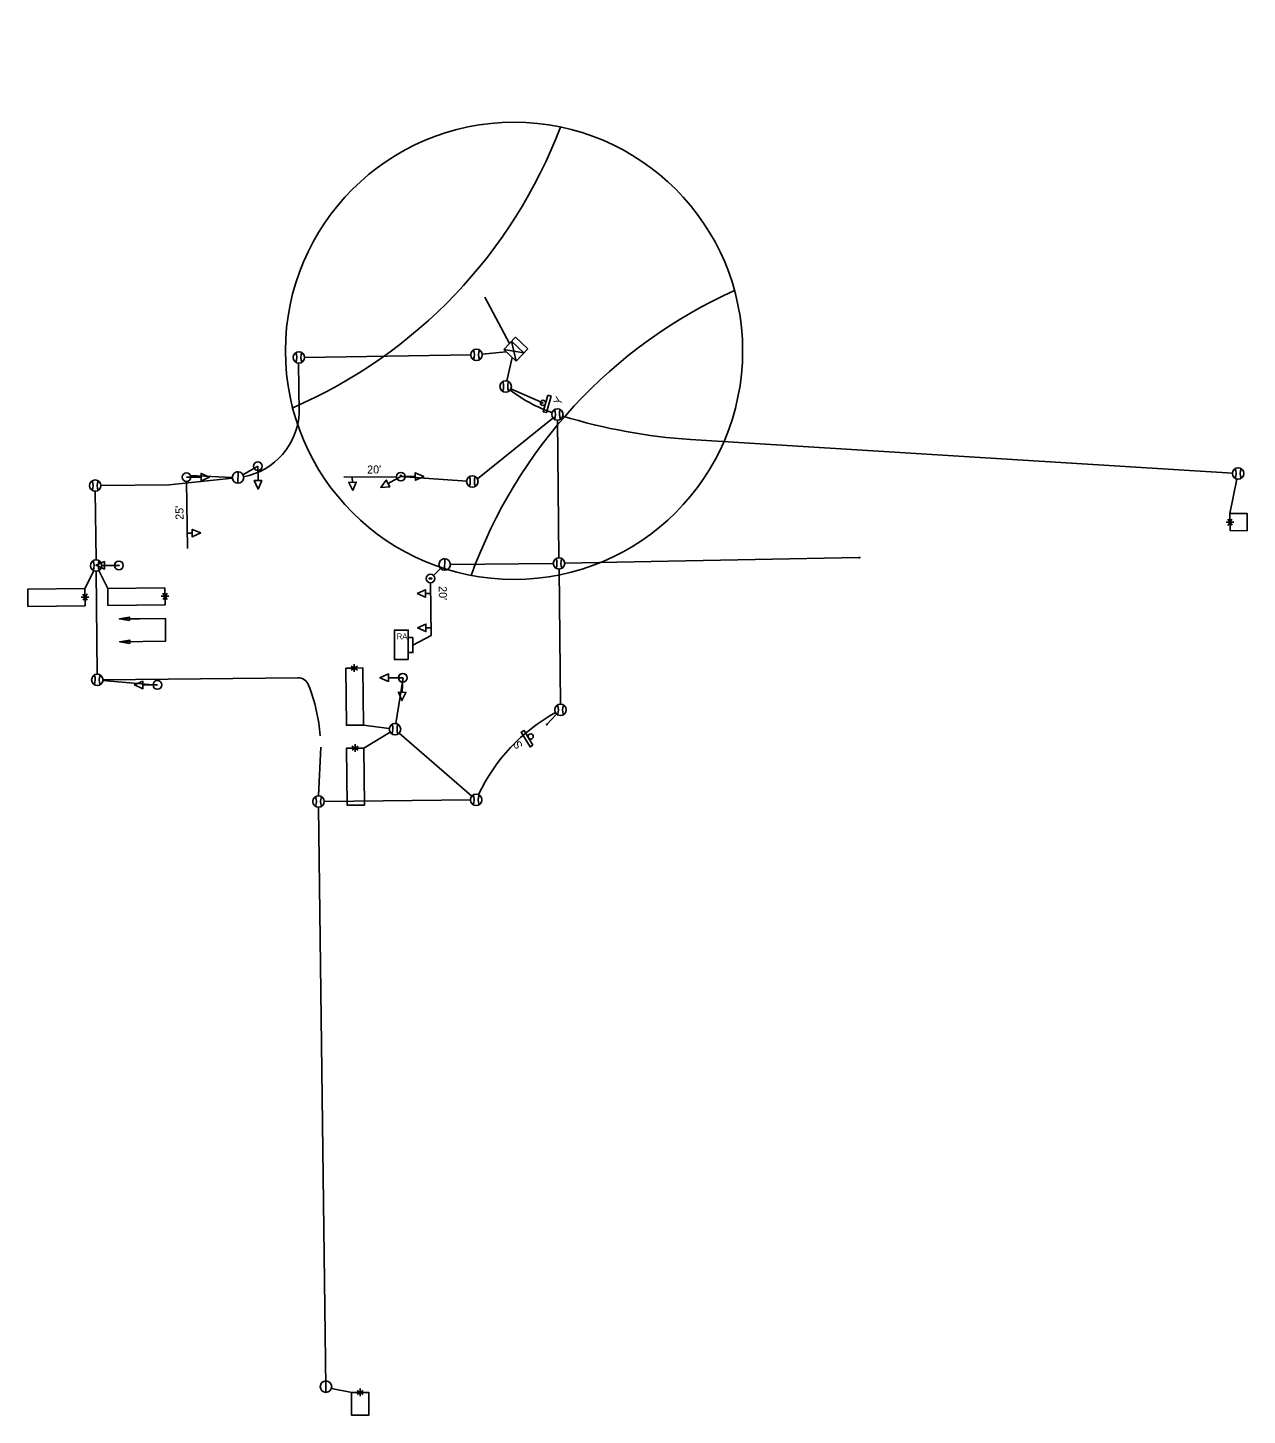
# Model space of a CAD drawing. Extents: x 596176 to 605330, y 332416 to 402398.
# Drawn here: x 602947 to 603373.8, y 387341.9 to 387827.4 of the extents above; entities that cross this region are included whole.
import ezdxf

# ---------------------------------------------------------------- set-up
doc = ezdxf.new("R2010")
doc.units = 0
for name, color, linetype in [('P_LTG', 7, 'Continuous'), ('P_SIG', 7, 'Continuous'), ('P_SIG_Bold', 7, 'Continuous'), ('P_SIG_Conduit', 7, 'Continuous'), ('P_SIG_IC', 7, 'Continuous'), ('P_SIG_Loops', 7, 'Continuous')]:
    doc.layers.add(name, color=color, linetype=linetype)

# ---------------------------------------------------------------- blocks, each defined once
blk = doc.blocks.new('_U305')
at = {"layer": 'P_SIG_Loops'}
for p, q in [((0.1, -0.1), (-0.1, 0.1)), ((-0.1, -0.1), (0.1, 0.1)), ((0, 0), (0, -0.2)), ((-0.1, 0), (0.1, 0))]:
    blk.add_line(p, q, dxfattribs=at)
blk.add_lwpolyline([(0, -0.2), (1.5, -0.2), (1.5, 0.2), (0, 0.2)], close=True, dxfattribs=at)
blk = doc.blocks.new('_U307')
at = {"layer": 'P_SIG_Loops'}
for p, q in [((0, 0), (0, -0.2)), ((0.6, -0.3), (0.5, -0.1)), ((0.5, -0.3), (0.6, -0.1)), ((0.5, -0.2), (0.7, -0.2))]:
    blk.add_line(p, q, dxfattribs=at)
blk.add_lwpolyline([(0, -0.2), (1.1, -0.2), (1.1, 0.2), (0, 0.2)], close=True, dxfattribs=at)
blk = doc.blocks.new('_U300')
at = {"layer": 'P_SIG_Bold'}
for p, q in [((-3, 0), (-0.1, 0)), ((-0.1, 0.1), (0.1, -0.1)), ((0.1, 0.1), (-0.1, -0.1))]:
    blk.add_line(p, q, dxfattribs=at)
blk.add_circle((0, 0), 0.114, dxfattribs=at)
blk.add_text("40'", height=0.213, dxfattribs=at).set_placement((-1.8, 0.1))
blk = doc.blocks.new('_U212')
at = {"layer": 'P_SIG'}
blk.add_circle((-0.002, 0.01), 6.096, dxfattribs=at)
for centre, start, end in [((-15.457, 0.118), 336.6741, 22.5272), ((15.453, 0.146), 157.5751, 203.4282)]:
    blk.add_arc(centre, 13.28, start, end, dxfattribs=at)

msp = doc.modelspace()

# ---------------------------------------------------------------- linework, layer by layer
at = {"layer": 'P_SIG'}
for p, q in [((603113.57, 387714.85), (603117.7, 387719.19)), ((603117.91, 387710.71), (603113.57, 387714.85)), ((603113.57, 387714.85), (603120.67, 387713.61)), ((603116.32, 387717.74), (603120.67, 387713.61)), ((603117.91, 387710.71), (603116.32, 387717.74)), ((603117.7, 387719.19), (603122.05, 387715.06)), ((603122.05, 387715.06), (603117.91, 387710.71)), ((603127.4, 387693.05), (603128.98, 387698.83)), ((603130.14, 387698.52), (603128.55, 387692.73)), ((603128.98, 387698.83), (603130.14, 387698.52)), ((603128.55, 387692.73), (603127.4, 387693.05)), ((603020.6, 387672.01), (603020.57, 387668.01)), ((603027.59, 387668.97), (603027.54, 387674.02)), ((603007.63, 387670.14), (603002.58, 387670.15)), ((603060.63, 387668.38), (603060.58, 387670.15)), ((603073.12, 387667.95), (603077.58, 387670.33)), ((603082.64, 387670.38), (603077.58, 387670.33)), ((603004.56, 387650.57), (603002.79, 387650.54)), ((602973.85, 387639.3), (602978.91, 387639.29)), ((603092.92, 387641.56), (603092.9, 387637.56)), ((603086.24, 387629.44), (603088.02, 387629.44)), ((603081.78, 387611.38), (603088.17, 387614.69)), ((603086.37, 387617.44), (603088.14, 387617.44)), ((603073.2, 387599.97), (603078.26, 387599.95)), ((603078.05, 387594.9), (603078.26, 387599.95)), ((602987.29, 387597.44), (602992.35, 387597.43)), ((603119.67, 387580.88), (603120.69, 387581.5)), ((603122.78, 387575.75), (603119.67, 387580.88)), ((603120.69, 387581.5), (603123.81, 387576.37)), ((603123.81, 387576.37), (603122.78, 387575.75)), ((603051.37, 387353.85), (603051.35, 387349.85))]:
    msp.add_line(p, q, dxfattribs=at)
for points in [[(603128.98, 387698.83), (603130.14, 387698.52), (603128.55, 387692.73), (603127.4, 387693.05)], [(603060.72, 387665.43), (603059.32, 387668.34), (603061.95, 387668.42)], [(603007.52, 387650.62), (603004.58, 387649.25), (603004.54, 387651.89)], [(603083.29, 387629.44), (603086.24, 387630.76), (603086.24, 387628.13)], [(603083.41, 387617.44), (603086.37, 387618.76), (603086.37, 387616.13)], [(603080.15, 387606.29), (603080.15, 387616.64), (603075.32, 387616.64), (603075.32, 387606.29)], [(603081.78, 387614.01), (603080.18, 387614.01), (603080.18, 387608.74), (603081.78, 387608.74)], [(603123.81, 387576.37), (603122.78, 387575.75), (603119.67, 387580.88), (603120.69, 387581.5)]]:
    msp.add_lwpolyline(points, close=True, dxfattribs=at)
for points in [[(603010.59, 387670.14), (603007.63, 387668.82), (603007.63, 387671.46), (603010.59, 387670.14)], [(603010.59, 387670.14), (603007.63, 387668.82), (603007.63, 387671.46), (603010.59, 387670.14)], [(603007.63, 387668.82), (603010.59, 387670.14), (603007.63, 387671.46), (603007.63, 387668.82)], [(603020.57, 387668.01), (603020.6, 387672.01)], [(603085.6, 387670.42), (603082.65, 387669.07), (603082.62, 387671.7), (603085.6, 387670.42)], [(603085.6, 387670.42), (603082.65, 387669.07), (603082.62, 387671.7), (603085.6, 387670.42)], [(603082.65, 387669.07), (603085.6, 387670.42), (603082.62, 387671.7), (603082.65, 387669.07)], [(603027.62, 387666.01), (603026.27, 387668.95), (603028.91, 387668.98), (603027.62, 387666.01)], [(603026.27, 387668.95), (603027.62, 387666.01), (603028.91, 387668.98), (603026.27, 387668.95)], [(603070.51, 387666.55), (603072.49, 387669.11), (603073.74, 387666.79), (603070.51, 387666.55)], [(603070.51, 387666.55), (603072.49, 387669.11), (603073.74, 387666.79), (603070.51, 387666.55)], [(603072.49, 387669.11), (603070.51, 387666.55), (603073.74, 387666.79), (603072.49, 387669.11)], [(602970.89, 387639.3), (602973.85, 387640.62), (602973.85, 387637.98), (602970.89, 387639.3)], [(602973.85, 387640.62), (602970.89, 387639.3), (602973.85, 387637.98), (602973.85, 387640.62)], [(603092.9, 387637.56), (603092.92, 387641.56)], [(602984.33, 387597.44), (602987.29, 387598.76), (602987.29, 387596.12), (602984.33, 387597.44)], [(602987.29, 387598.76), (602984.33, 387597.44), (602987.29, 387596.12), (602987.29, 387598.76)], [(603070.24, 387599.97), (603073.2, 387601.28), (603073.2, 387598.65), (603070.24, 387599.97)], [(603073.2, 387601.28), (603070.24, 387599.97), (603073.2, 387598.65), (603073.2, 387601.28)], [(603077.93, 387591.94), (603076.73, 387594.95), (603079.37, 387594.85), (603077.93, 387591.94)], [(603076.73, 387594.95), (603077.93, 387591.94), (603079.37, 387594.85), (603076.73, 387594.95)], [(603051.35, 387349.85), (603051.37, 387353.85)]]:
    msp.add_lwpolyline(points, dxfattribs=at)
for centre, radius in [((603104.04, 387712.98), 2), ((603041.89, 387712.06), 2), ((603114.25, 387701.88), 2), ((603127.32, 387696.16), 0.9), ((603132.36, 387692.11), 2), ((603020.59, 387670.01), 2), ((603027.54, 387674.02), 1.52), ((603027.54, 387674.02), 1.52), ((603027.54, 387674.02), 1.52), ((603370.59, 387671.45), 2), ((602970.61, 387667.2), 2), ((603102.6, 387668.65), 2), ((603132.91, 387639.98), 2), ((602970.9, 387639.21), 2), ((602978.91, 387639.29), 1.52), ((602978.91, 387639.29), 1.52), ((602978.91, 387639.29), 1.52), ((603092.91, 387639.56), 2), ((602971.33, 387599.2), 2), ((602992.35, 387597.43), 1.52), ((602992.35, 387597.43), 1.52), ((602992.35, 387597.43), 1.52), ((603078.26, 387599.95), 1.52), ((603078.26, 387599.95), 1.52), ((603078.26, 387599.95), 1.52), ((603078.26, 387599.95), 1.52), ((603078.26, 387599.95), 1.52), ((603078.26, 387599.95), 1.52), ((603133.45, 387588.72), 2), ((603075.52, 387581.93), 2), ((603123.01, 387579.41), 0.9), ((603048.78, 387556.64), 2), ((603103.93, 387557.22), 2), ((603051.36, 387351.85), 2)]:
    msp.add_circle(centre, radius, dxfattribs=at)
for centre, radius, start, end in [((603036.82, 387712.1), 4.36, 336.6741, 22.5272), ((603046.97, 387712.11), 4.36, 157.5751, 203.4282), ((603098.97, 387713.01), 4.36, 336.6741, 22.5272), ((603109.11, 387713.02), 4.36, 157.5751, 203.4282), ((603109.18, 387701.92), 4.36, 336.6741, 22.5272), ((603119.32, 387701.93), 4.36, 157.5751, 203.4282), ((603127.29, 387692.14), 4.36, 336.6741, 22.5272), ((603137.43, 387692.15), 4.36, 157.5751, 203.4282), ((603020.59, 387670.01), 2, 89.7008, 180), ((603027.54, 387674.02), 1.52, 90.7054, 270.7054), ((603027.54, 387674.02), 1.52, 270.7054, 90.7054), ((603365.51, 387671.48), 4.36, 336.6741, 22.5272), ((603375.66, 387671.49), 4.36, 157.5751, 203.4282), ((602965.54, 387667.24), 4.36, 336.6741, 22.5272), ((602975.68, 387667.25), 4.36, 157.5751, 203.4282), ((603020.59, 387670.01), 2, 180, 269.7008), ((603097.53, 387668.69), 4.36, 336.6741, 22.5272), ((603107.67, 387668.7), 4.36, 157.5751, 203.4282), ((602965.83, 387639.24), 4.36, 336.6741, 22.5272), ((602975.98, 387639.25), 4.36, 157.5751, 203.4282), ((602978.91, 387639.29), 1.52, 0, 180), ((602978.91, 387639.29), 1.52, 180, 0), ((603092.91, 387639.56), 2, 89.7008, 180), ((603092.91, 387639.56), 2, 180, 269.7008), ((603127.84, 387640.02), 4.36, 336.6741, 22.5272), ((603137.98, 387640.03), 4.36, 157.5751, 203.4282), ((602966.26, 387599.24), 4.36, 336.6741, 22.5272), ((602976.4, 387599.25), 4.36, 157.5751, 203.4282), ((602992.35, 387597.43), 1.52, 0, 180), ((603078.26, 387599.95), 1.52, 87.7274, 267.7274), ((603078.26, 387599.95), 1.52, 0, 180), ((603078.26, 387599.95), 1.52, 180, 0), ((603078.26, 387599.95), 1.52, 267.7274, 87.7274), ((602992.35, 387597.43), 1.52, 180, 0), ((603128.38, 387588.75), 4.36, 336.6741, 22.5272), ((603138.52, 387588.76), 4.36, 157.5751, 203.4282), ((603070.44, 387581.96), 4.36, 336.6741, 22.5272), ((603080.59, 387581.97), 4.36, 157.5751, 203.4282), ((603043.71, 387556.67), 4.36, 336.6741, 22.5272), ((603053.85, 387556.68), 4.36, 157.5751, 203.4282), ((603098.86, 387557.25), 4.36, 336.6741, 22.5272), ((603109, 387557.26), 4.36, 157.5751, 203.4282), ((603051.36, 387351.85), 2, 89.7008, 180), ((603051.36, 387351.85), 2, 180, 269.7008)]:
    msp.add_arc(centre, radius, start, end, dxfattribs=at)
at = {"layer": 'P_SIG_Bold'}
for p, q in [((603002.85, 387645.15), (603002.59, 387668.65)), ((603057.58, 387670.12), (603076.08, 387670.32)), ((603088.17, 387614.69), (603087.98, 387633.19))]:
    msp.add_line(p, q, dxfattribs=at)
for centre in [(603002.58, 387670.15), (603077.58, 387670.33), (603087.96, 387634.69)]:
    msp.add_circle(centre, 1.5, dxfattribs=at)
at = {"layer": 'P_SIG_Conduit'}
for p, q in [((603043.89, 387712.09), (603102.04, 387712.95)), ((603114.48, 387713.98), (603106.03, 387713.17)), ((603114.7, 387703.83), (603116.58, 387711.98)), ((603127.31, 387696.15), (603116.08, 387701.08)), ((603104.38, 387669.57), (603130.8, 387690.85)), ((603132.89, 387641.98), (603132.38, 387690.11)), ((603027.54, 387674.02), (603022.32, 387671.01)), ((603003.95, 387670.75), (603018.59, 387670.06)), ((603100.61, 387668.79), (603079.08, 387670.27)), ((602970.63, 387665.2), (602970.88, 387641.21)), ((603237.89, 387642.03), (603134.91, 387640)), ((602970.93, 387637.21), (602971.31, 387601.2)), ((603094.91, 387639.58), (603130.91, 387639.96)), ((603133.43, 387590.72), (603132.93, 387637.98)), ((602973.32, 387599.03), (602992.15, 387597.42)), ((603075.82, 387583.9), (603078.33, 387599.95)), ((603077, 387580.59), (603102.42, 387558.53)), ((603101.93, 387557.19), (603051.02, 387556.66))]:
    msp.add_line(p, q, dxfattribs=at)
for points in [[(603042.01, 387692.77), (603041.8, 387710.06)], [(603178.95, 387683.33), (603368.59, 387671.61), (603368.59, 387671.61)], [(602972.62, 387667.22), (602996.51, 387667.51), (603018.6, 387669.8)], [(603022.47, 387670.28), (603022.47, 387670.28), (603022.47, 387670.28)], [(602972.9, 387639.22), (602978.91, 387639.29)], [(603089.01, 387635.77), (603091.48, 387638.16)], [(602973.33, 387599.23), (603041.53, 387599.95)], [(603128.51, 387583.51), (603132.07, 387587.27)], [(603048.76, 387558.64), (603049.52, 387575.65)], [(603051.36, 387351.84), (603048.8, 387554.64)]]:
    msp.add_lwpolyline(points, dxfattribs=at)
for centre, radius, start, end in [((603148.38, 387743.44), 53.78, 232.7335, 250.5354), ((603018.04, 387693.87), 24, 280.6527, 357.3808), ((603192.24, 387881.94), 199.06, 253.0679, 266.1721), ((603041.57, 387595.95), 4, 21.0949, 90.6076), ((602985.59, 387574.35), 64, 4.7442, 21.0949), ((603162.64, 387531.76), 64, 118.9265, 154.7678)]:
    msp.add_arc(centre, radius, start, end, dxfattribs=at)
at = {"layer": 'P_SIG_IC'}
msp.add_line((603115.61, 387716.99), (603106.99, 387733.18), dxfattribs=at)
at = {"layer": 'P_SIG_Loops'}
for p, q in [((603367.73, 387657.39), (603370.19, 387669.48)), ((603366.39, 387654.36), (603369.07, 387654.39)), ((603367.06, 387653.28), (603368.44, 387655.47)), ((603368.51, 387653.31), (603367.06, 387655.46)), ((603367.77, 387654.39), (603367.8, 387651.39)), ((602966.99, 387631.16), (602970.07, 387637.39)), ((602971.86, 387637.45), (602974.99, 387631.24)), ((602968.4, 387628.19), (602965.72, 387628.16)), ((602966.28, 387629.25), (602967.73, 387627.09)), ((602967.73, 387629.27), (602966.35, 387627.08)), ((602967.02, 387628.16), (602966.99, 387631.16)), ((602996.4, 387628.49), (602993.72, 387628.46)), ((602994.28, 387629.54), (602995.73, 387627.38)), ((602995.73, 387629.57), (602994.35, 387627.38)), ((602995.02, 387628.46), (602994.99, 387631.46)), ((603061.29, 387603.34), (603058.29, 387603.31)), ((603060.18, 387604.05), (603062.36, 387602.66)), ((603060.2, 387602.59), (603062.36, 387604.05)), ((603061.26, 387604.71), (603061.28, 387602.03)), ((603073.53, 387582.18), (603064.5, 387583.37)), ((603064.59, 387575.37), (603073.79, 387580.92)), ((603061.59, 387575.34), (603058.59, 387575.31)), ((603060.47, 387576.05), (603062.66, 387574.66)), ((603060.5, 387574.6), (603062.66, 387576.05)), ((603061.55, 387576.71), (603061.58, 387574.03)), ((603060.38, 387349.87), (603053.28, 387351.28)), ((603062.23, 387350.58), (603064.41, 387349.18)), ((603062.25, 387349.13), (603064.42, 387350.56)), ((603063.32, 387351.24), (603063.32, 387348.56)), ((603063.34, 387349.87), (603060.34, 387349.86))]:
    msp.add_line(p, q, dxfattribs=at)
for points in [[(603367.8, 387651.39), (603373.8, 387651.45), (603373.73, 387657.45), (603367.73, 387657.39)], [(602966.99, 387631.16), (602946.99, 387630.95), (602947.06, 387624.95), (602967.06, 387625.16)], [(602994.99, 387631.46), (602974.99, 387631.24), (602975.05, 387625.25), (602995.05, 387625.46)], [(602982.61, 387619.99), (602979.1, 387620.54), (602982.6, 387621.16)], [(602982.69, 387611.99), (602979.19, 387612.54), (602982.68, 387613.16)], [(603058.29, 387603.31), (603058.5, 387583.31), (603064.5, 387583.37), (603064.29, 387603.37)], [(603058.59, 387575.31), (603058.8, 387555.31), (603064.8, 387555.37), (603064.59, 387575.37)], [(603060.34, 387349.86), (603060.35, 387341.86), (603066.35, 387341.87), (603066.34, 387349.87)]]:
    msp.add_lwpolyline(points, close=True, dxfattribs=at)
for points in [[(602979.19, 387612.54), (602995.15, 387612.71), (602995.15, 387620.71), (602979.1, 387620.54)], [(602982.6, 387620.57), (602986.25, 387620.61)], [(602982.69, 387612.58), (602986.34, 387612.61)]]:
    msp.add_lwpolyline(points, dxfattribs=at)

# ---------------------------------------------------------------- block references
at = {"layer": 'P_LTG'}
for name, p, xscale, yscale, rotation in [('_U307', (603127.31, 387696.15), 0.32808333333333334, 0.32808333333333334, 161.58094653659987), ('_U305', (603077.58, 387670.33), 0.3280833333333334, 0.32808333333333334, 90.76868372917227), ('_U307', (603237.89, 387642.03), 0.32808333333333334, 0.32808333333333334, 0.7575539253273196), ('_U305', (603087.96, 387634.69), 0.32808333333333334, 0.32808333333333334, 179.99999999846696), ('_U305', (603087.96, 387634.69), 0.32808333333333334, 0.3280833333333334, 0.7575548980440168), ('_U307', (603128.51, 387583.51), 0.32808333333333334, 0.32808333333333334, 31.820917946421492)]:
    msp.add_blockref(name, p, dxfattribs=dict(at, xscale=xscale, yscale=yscale, rotation=rotation))
at = {"layer": 'P_LTG', "xscale": 0.32808333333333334, "yscale": 0.32808333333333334}
msp.add_blockref('_U300', (602978.91, 387639.29), dxfattribs=at)
at = {"layer": 'P_SIG_Bold', "xscale": 13.123333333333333, "yscale": 13.123333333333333, "rotation": -43.244046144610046}
msp.add_blockref('_U212', (603117.12, 387714.23), dxfattribs=at)

# ---------------------------------------------------------------- texts
at = {"layer": 'P_SIG'}
for s, height, rotation, p in [('Y', 2.8, 63.9173, (603133.41, 387695.17)), ('RA', 2, 360, (603076.14, 387613.45)), ('S', 2.8, 121.2641, (603120.39, 387576.06))]:
    msp.add_text(s, height=height, rotation=rotation, dxfattribs=at).set_placement(p)
at = {"layer": 'P_SIG_Bold'}
for s, rotation, p in [("20'", 0.6076, (603065.81, 387671.42)), ("25'", 90.623, (603001.52, 387655.27)), ("20'", 270.6076, (603090.84, 387631.99))]:
    msp.add_text(s, height=2.8, rotation=rotation, dxfattribs=at).set_placement(p)

doc.saveas('drawing.dxf')
